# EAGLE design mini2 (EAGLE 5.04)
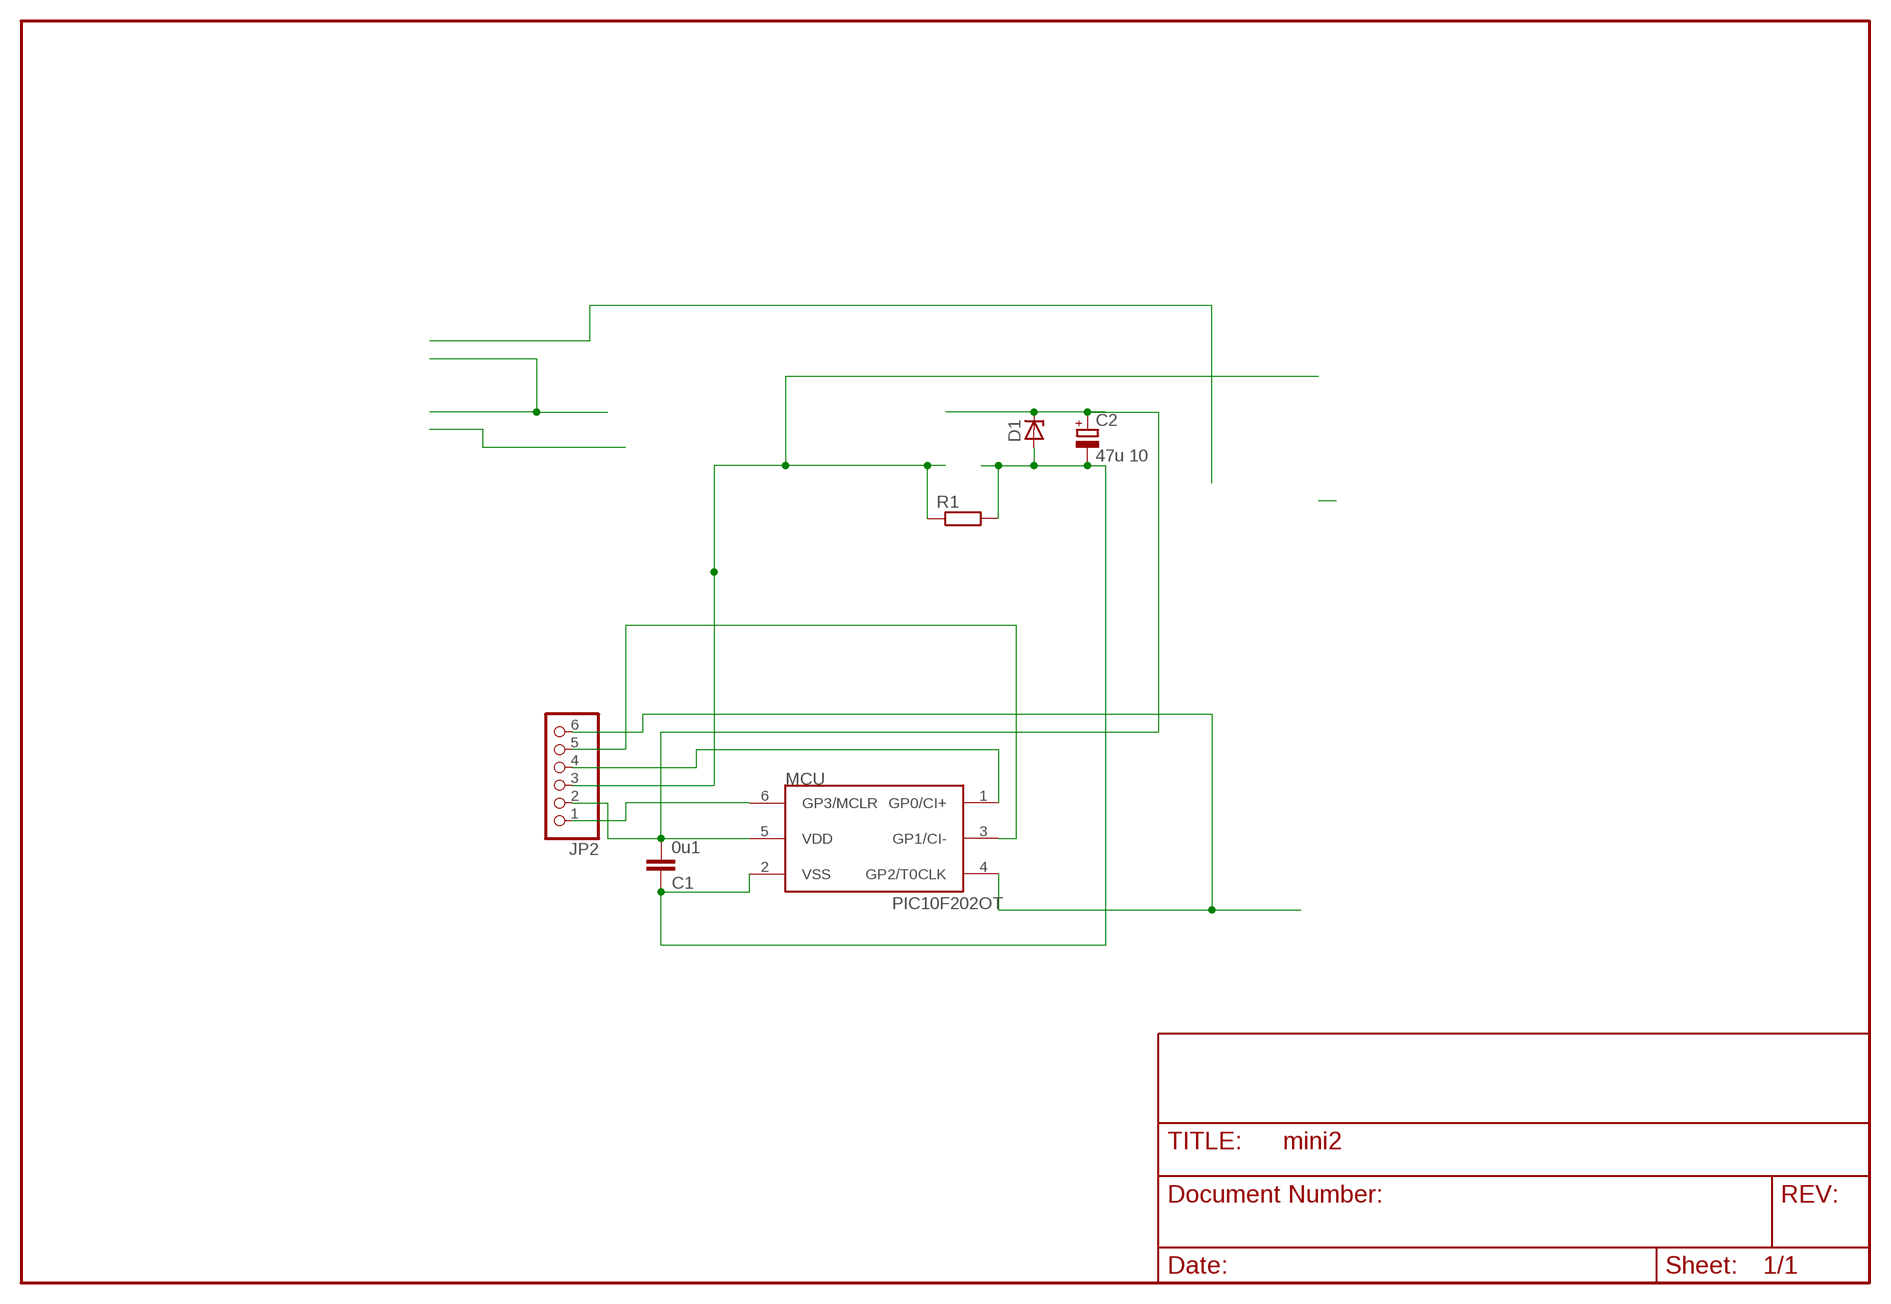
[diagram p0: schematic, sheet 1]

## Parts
C1  0u1  C-EUC0805  [C0805]
C2  47u 10  CPOL-EUE2-5  [E2-5]
D1  ZENER-DIODESOT23  [SOT23]
JP2  PINHD-1X6  [1X06]
MCU  PIC10F202OT  [SOT23-6]
R1  R-EU_R1206  [R1206]

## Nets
GATE: JP2.6 MCU.4(GP2/T0CLK)
GP0: JP2.4 MCU.1(GP0/CI+)
GP1: JP2.5 MCU.3(GP1/CI-)
GP3: JP2.1 MCU.6(GP3/MCLR)
N$2: C1.1 C2.- D1.1(A) MCU.2(VSS) R1.2
VDD: C1.2 C2.+ D1.3(C) JP2.2 MCU.5(VDD)
VSS: JP2.3 R1.1

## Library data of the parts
C1 = rcl:C-EU: CAPACITOR, European symbol
C2 = rcl:CPOL-EU: POLARIZED CAPACITOR, European symbol
D1 = diode-1:ZENER-DIODE: Z-Diode
JP2 = pinhead:PINHD-1X6: PIN HEADER
MCU = microchip-3:PIC10F2*: uPC nW 0,25/0,5k Program Flash memory Comparator
R1 = rcl-2:R-EU_: RESISTOR, European symbol

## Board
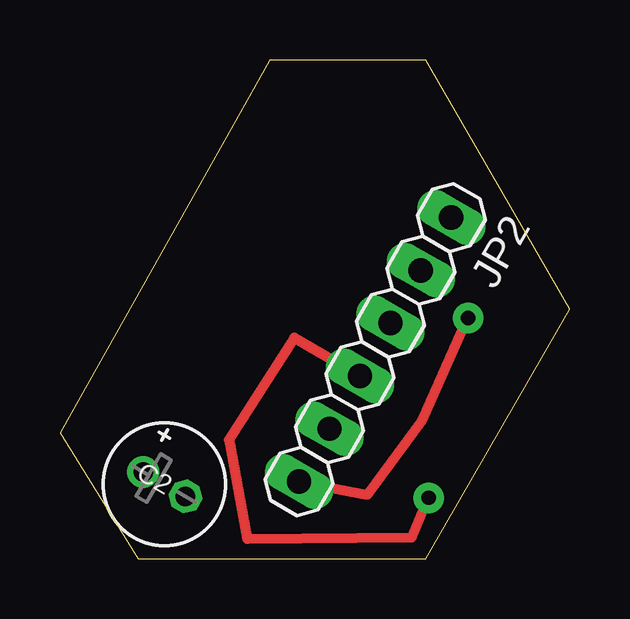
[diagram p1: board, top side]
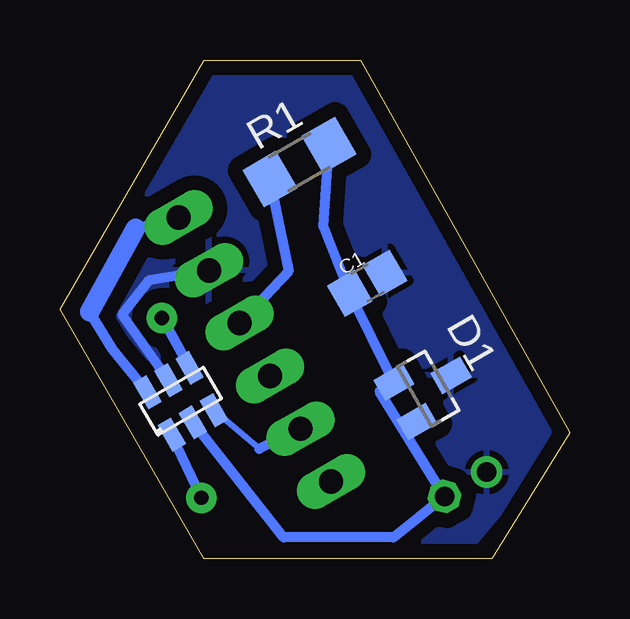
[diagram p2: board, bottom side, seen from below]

Size 21.27 x 20.78 mm. Coordinates in mm from the lower left corner, seen from the top.
Outline: 3.27,0 15.27,0 21.27,10.39 15.27,20.78 8.73,20.78 0,5.25 3.27,0
Copper layers (1*16): Top 0.035mm / dielectric 1.5mm / Bottom 0.035mm
Design rules "default": minimum track width 10mil, minimum drill 24mil, track to track 8mil, track to pad 8mil, pad to pad 8mil, via to via 8mil, smd to smd 8mil, copper to edge 8mil, drill to drill 8mil, minimum pad ring 10mil, minimum via ring 8mil, stop-mask expansion 4mil, vias tented up to drill 0mil, thermal gap 10mil

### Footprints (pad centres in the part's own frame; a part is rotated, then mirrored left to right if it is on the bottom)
C0805 = smd 1.3 x 1.5: 1 -0.85,0; 2 0.85,0
E2-5 = drill 0.813 pad 1.27 round: + -1.016,0 | drill 0.813 pad 1.27 octagon: - 1.016,0
SOT23 = smd 1 x 1.4: 1 -0.95,-1.1; 2 0.95,-1.1; 3 0,1.1
1X06 = drill 1.016 long: 1 -6.35,0; 2 -3.81,0; 3 -1.27,0; 4 1.27,0; 5 3.81,0; 6 6.35,0
SOT23-6 = smd 0.635 x 1.27: 1 -1.016,-1.016; 2 0,-1.016; 3 1.016,-1.016; 4 1.016,1.016; 5 0,1.016; 6 -1.016,1.016
R1206 = smd 1.6 x 1.803: 1 -1.422,0; 2 1.422,0

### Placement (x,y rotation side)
C1  8.45,11.48 30 bottom
C2  4.35,3.1 330 top
D1  5.91,7.09 300 bottom
JP2  13.14,8.72 240 top
MCU  16.24,6.56 30 bottom
R1  11.28,16.53 30 bottom

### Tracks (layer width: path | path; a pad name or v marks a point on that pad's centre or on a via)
GATE  (via drill 0.6 pad 1.27)
  Top 0.406: v17.02,10.03 15.11,5.78 12.83,2.67 JP2.6
  Bottom 0.406: v17.02,10.03 MCU.4
GP0  (via drill 0.6 pad 1.27)
  Top 0.406: v15.37,2.54 14.67,0.89 7.81,0.83 7.05,4.95 9.78,9.21 JP2.4
  Bottom 0.406: v15.37,2.54 MCU.1
GP1
  Bottom 0.254: 12.95,4.57 MCU.3
  Bottom 0.406: JP2.5 12.95,4.57
GP3
  Bottom 0.406: MCU.6 19.08,8.73 20.03,10.29 | 18.11,13.78 JP2.1
  Bottom 0.813: 20.03,10.29 18.11,13.78
N$2
  Bottom 0.406: MCU.2 11.94,0.89 7.37,0.89 C2.- 7.94,6.99 D1.1 C1.1 10.29,13.84 R1.2
VDD
  Bottom 0.406: MCU.5 18.67,10.16 17.53,11.62 JP2.2
  pour Bottom (isolate 0.61): 14.86,20.64 20.64,10.54 14.73,0.57 4.06,0.57 0.38,4.95 9.08,20.45
VSS
  Bottom 0.406: JP2.3 11.72,12.01 R1.1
